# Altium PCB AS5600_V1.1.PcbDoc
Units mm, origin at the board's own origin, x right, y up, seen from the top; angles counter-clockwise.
Board outline 34 x 34 mm, 2 copper layers (Top Layer, Bottom Layer); 12 components, 7 nets, 31 pads, 49 vias.
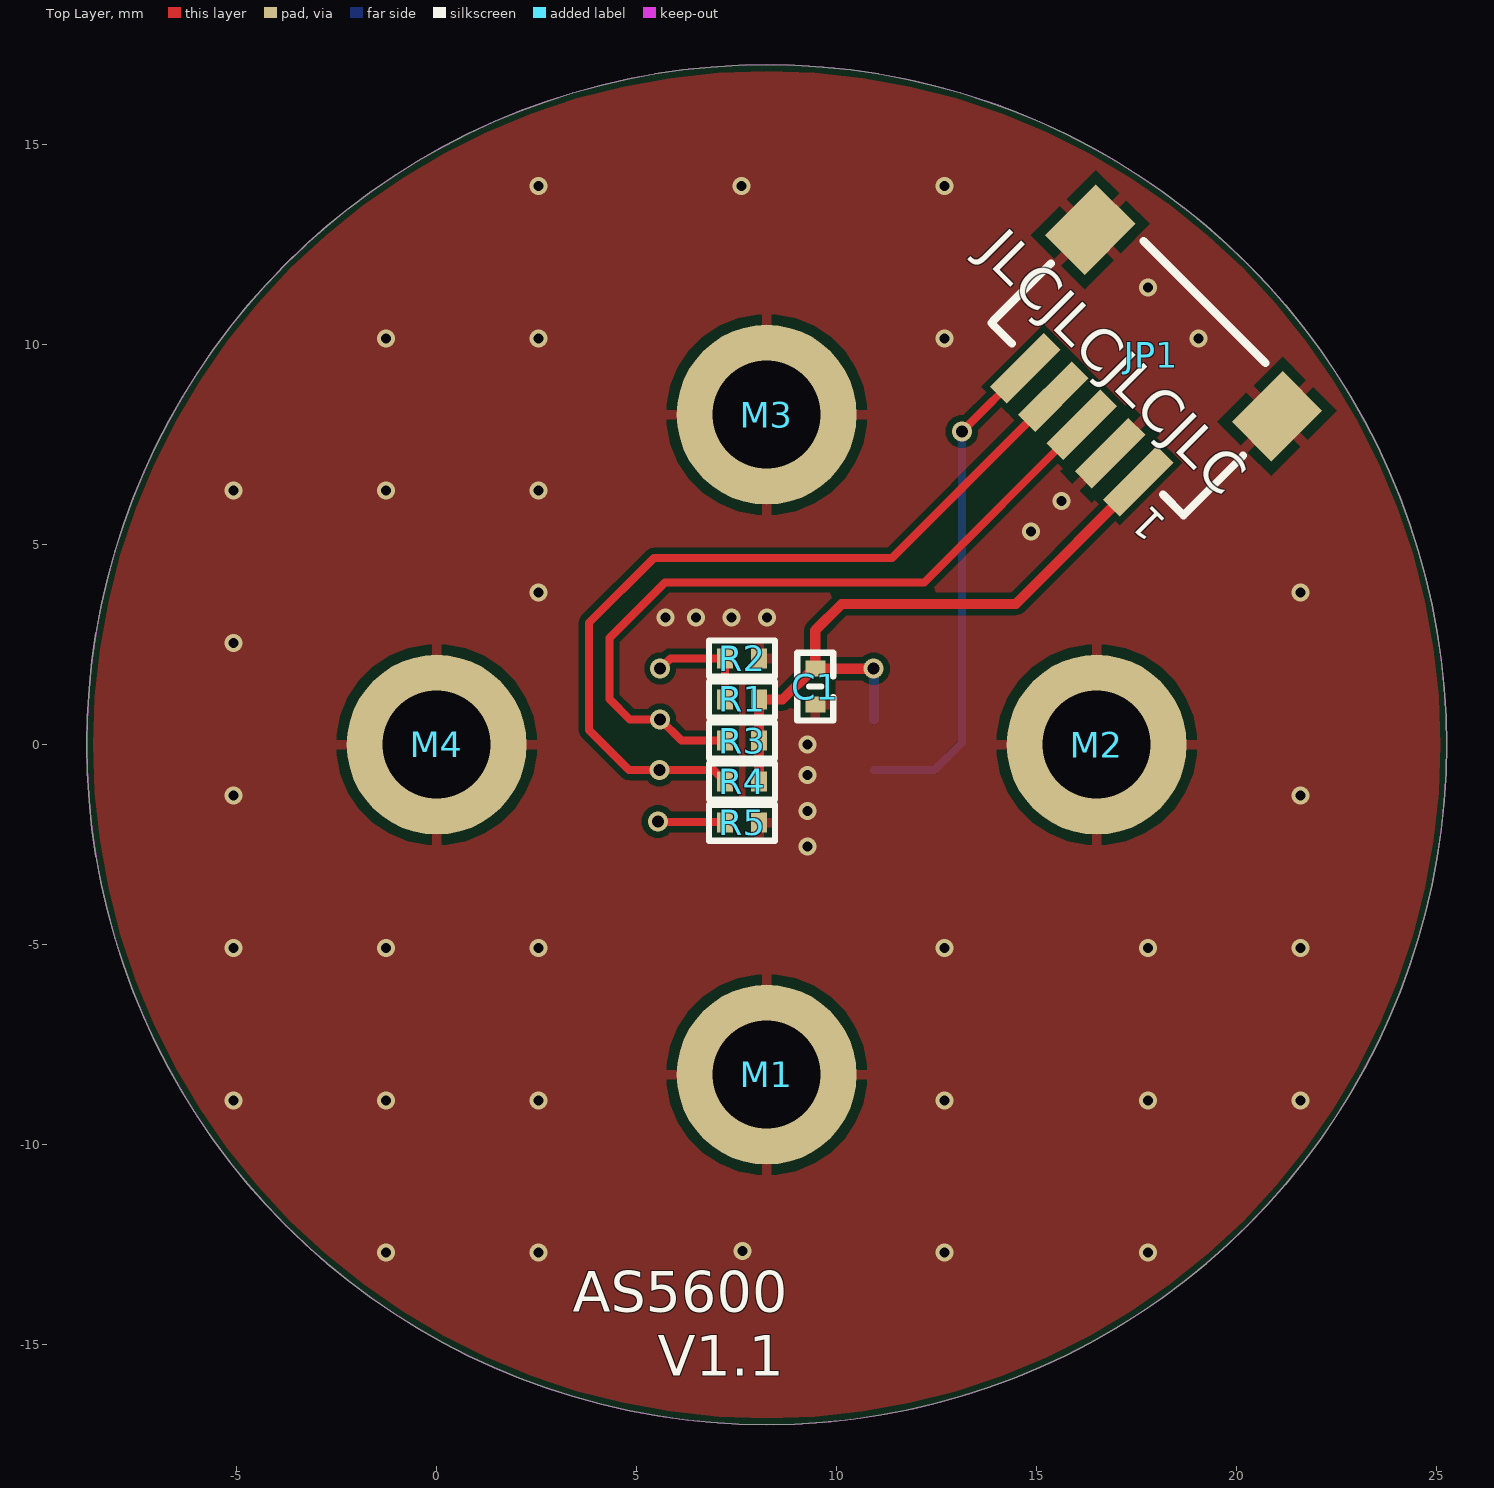
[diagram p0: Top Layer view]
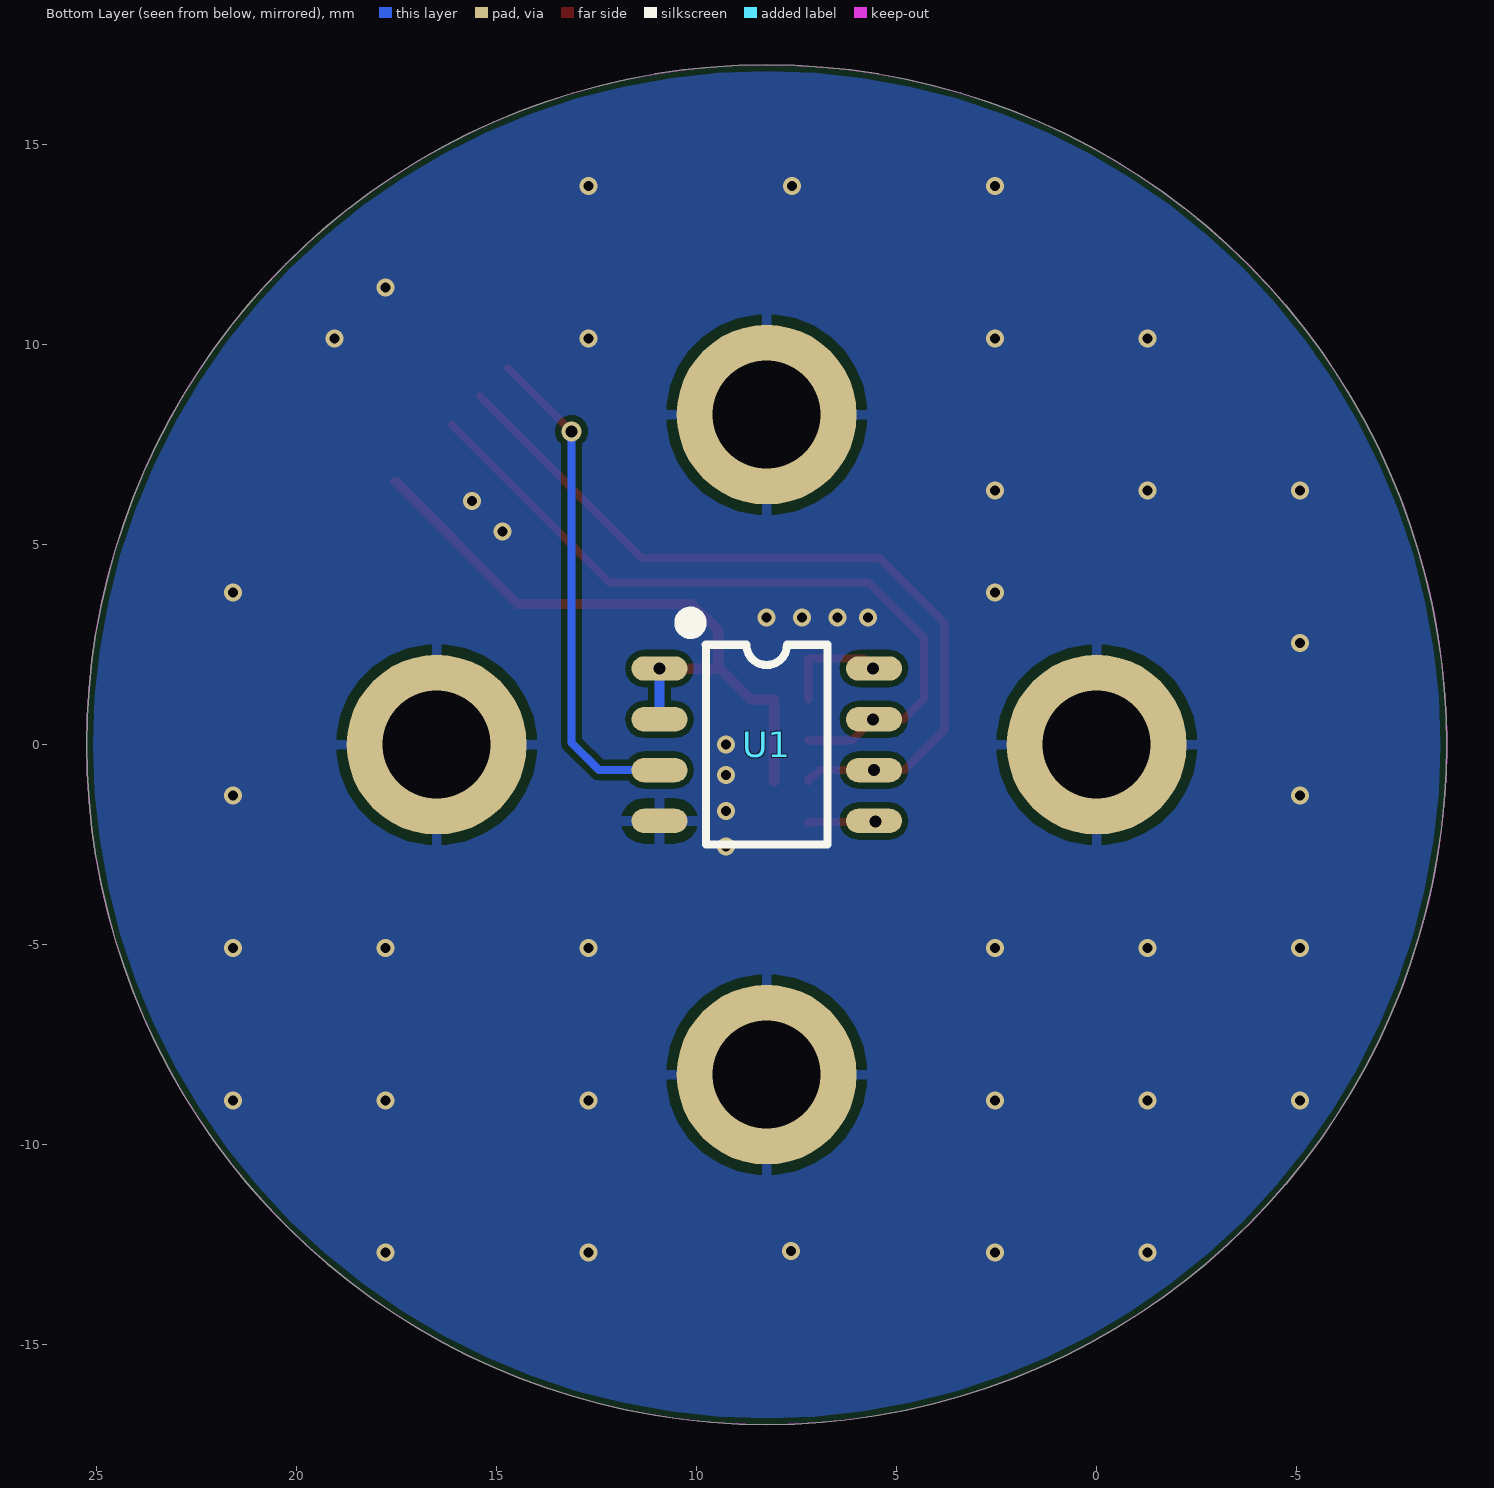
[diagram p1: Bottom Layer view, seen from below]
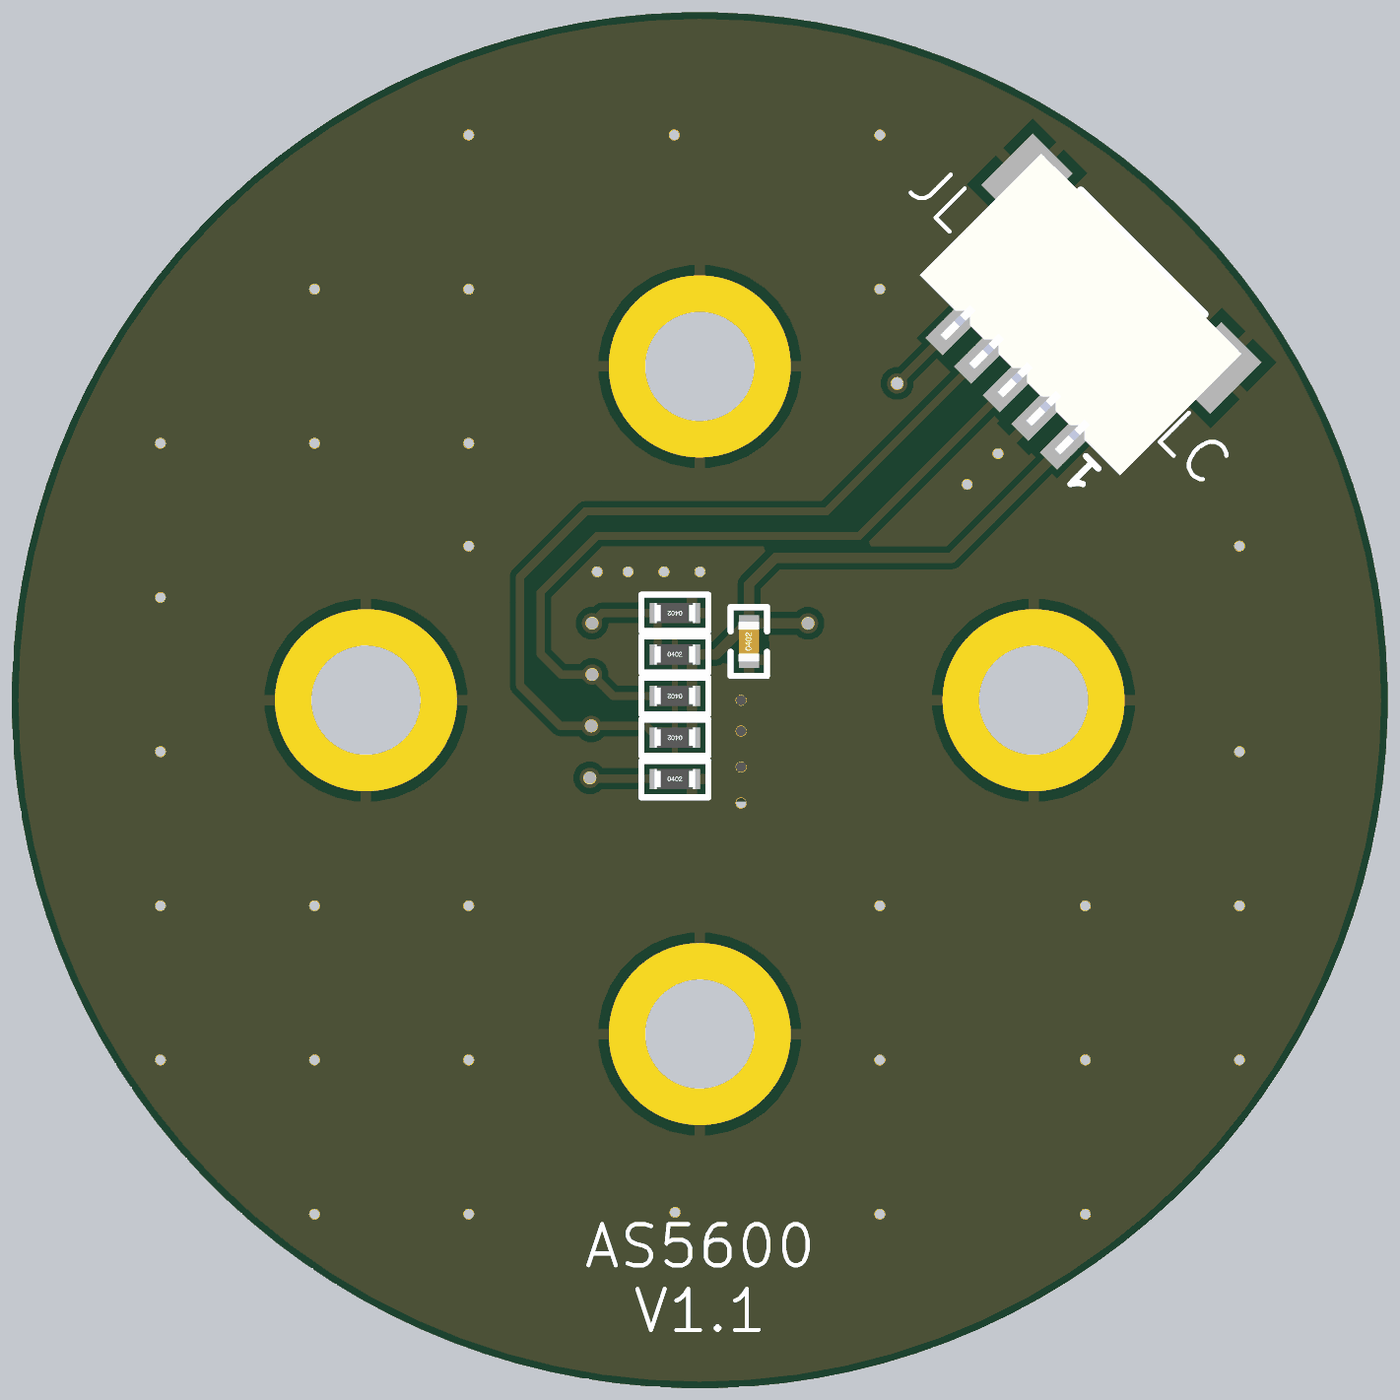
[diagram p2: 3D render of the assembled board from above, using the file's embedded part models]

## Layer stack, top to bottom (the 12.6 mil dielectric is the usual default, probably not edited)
Top Solder: solder mask 0.0102, Solder Resist, Dk 3.5
Top Layer: signal copper 0.0356
Dielectric 1: dielectric 0.32, FR-4, Dk 4.8
Bottom Layer: signal copper 0.0356
Bottom Solder: solder mask 0.0102, Solder Resist, Dk 3.5

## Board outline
-8.75,0 ccw(c8.25,0) 8.25,-17 ccw(c8.25,0) 25.25,0 ccw(c8.25,0) 8.25,17 ccw(c8.25,0)

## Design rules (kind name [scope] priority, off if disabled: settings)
Clearance [All] p1: gap=0.152 ignorepadtopadclearanceinfootprint=FALSE
HoleToHoleClearance [All] p1: gap=0 allowstackedmicrovias=TRUE
MinimumSolderMaskSliver [All] p1: minsoldermaskwidth=0
PolygonConnect M2.5 [HasFootprint('M2焊盘')] p1: connectstyle=Direct reliefconductorwidth=0.254 reliefentries=4 polygonreliefangle="90 Angle" airgapwidth=0.254
PolygonConnect [All] p2: thpad.connectstyle=Relief thpad.reliefconductorwidth=0.254 thpad.reliefentries=4 thpad.polygonreliefangle="90 Angle" thpad.airgapwidth=0.254 smdpad.connectstyle=Relief smdpad.reliefconductorwidth=0.254 smdpad.reliefentries=4 smdpad.polygonreliefangle="90 Angle" smdpad.airgapwidth=0.254 via.connectstyle=Direct via.reliefconductorwidth=0.254 via.reliefentries=4 via.polygonreliefangle="90 Angle" via.airgapwidth=0.254
RoomDefinition AS5600 [InComponentClass('AS5600')] p1: confinementstyle=ConfineIn formatcopy=TRUE lockcomponents=FALSE outline -75.128,-76.456 -24.328,-76.456 -24.328,-51.056 -75.128,-51.056
RoutingVias [All] p1: holewidth=0.25 width=0.45 viastyle="Through Hole" minholewidth=0.25 minwidth=0.45 maxholewidth=0.6 maxwidth=0.8
SilkToSilkClearance [All] p1: silktosilkclearance=0
SilkToSolderMaskClearance [IsPad] p1: minsilkscreentomaskgap=0 clearancetoexposedcopper=TRUE
SolderMaskExpansion [IsVia] p1: expansion=0.102 istentingtop=TRUE useseparateexpansions=TRUE expansionbottom=0.102 istentingbottom=TRUE
Width [All] p1: maxlimit=0.762 minlimit=0.152 preferedwidth=0.152
26 further rules are at their usual default settings.

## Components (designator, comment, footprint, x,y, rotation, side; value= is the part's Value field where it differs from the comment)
C1 "0.1uF" C0402_L 9.463,1.451 r90 top
JP1 "CON-5P" SH1.0-WT-5P 17.399,9.271 r135 top
M1 "M2.5" M2.5 8.25,-8.25 r0 top
M2 "M2.5" M2.5 16.5,0 r0 top
M3 "M2.5" M2.5 8.25,8.25 r0 top
M4 "M2.5" M2.5 0,0 r0 top
R1 "NC" R0402_L 7.635,1.132 r0 top
R2 "NC" R0402_L 7.635,2.159 r180 top
R3 "4.7K" R0402_L 7.635,0.105 r180 top
R4 "4.7K" R0402_L 7.635,-0.922 r180 top
R5 "4.7K" R0402_L 7.635,-1.95 r0 top
U1 "AS5600" SOIC-8L 8.25,0 r180 bottom locked

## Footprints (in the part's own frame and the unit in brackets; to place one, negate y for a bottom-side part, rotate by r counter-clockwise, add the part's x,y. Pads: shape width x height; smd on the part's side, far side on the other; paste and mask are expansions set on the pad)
C0402_L [mm] "无极性贴片电容"
  rect 0.4x0.5 smd: 1(-0.45,0) 2(0.45,0)
  silkscreen extent -0.85,-0.45 0.85,0.45, body extent -0.5,-0.26 0.5,0.26, height 0.54
M2.5 [mm]
  round 4.5 hole 2.7: 1(0,0)
R0402_L [mm] "1/16W贴片电阻"
  rect 0.4x0.5 smd: 1(-0.425,0) 2(0.425,0)
  silkscreen extent -0.82,-0.45 0.83,0.45, body extent -0.5,-0.25 0.5,0.25, height 0.3
SH1.0-WT-5P [mm] "SH1.0连接器-卧贴-5P      来自淘宝卖家ID：黄晶宝石"
  rect 1.4x1.8 smd: 0(-3.3,-1.8) 0(3.3,-1.8)
  rect 0.6x1.9 smd: 1(-2,1.8) 2(-1,1.8) 3(0,1.8) 4(1,1.8) 5(2,1.8)
  silkscreen extent -3.4,-2.54 3.4,1.6, body extent -3.5,-2.5 3.5,2.45, height 2.9
SOIC-8L [mm] "封装库来自淘宝卖家 ID：黄晶宝石，其他均为盗版"
  oval 1.397x0.61 smd: 1(-2.68,1.905) 2(-2.68,0.635) 3(-2.68,-0.635) 4(-2.68,-1.905) 5(2.68,-1.905) 6(2.68,-0.635) 7(2.68,0.635) 8(2.68,1.905)
  silkscreen extent -2.06,-2.5 1.52,3.2, body extent -3,-2.5 3,2.5, height 1.9

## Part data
C1: library part C, "贴片电容"
JP1: library part "Header 5", "5P连接器"
M1 M2 M3 M4: library part M2系列, "M2孔支撑柱"
R1 R2 R3 R4 R5: library part R, "贴片电阻"
U1: "12bit 磁编码器"

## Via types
v1: diameter 0.45, hole 0.25, Top Layer to Bottom Layer, tented both sides, 43 vias
v2: diameter 0.5, hole 0.3, Top Layer to Bottom Layer, tented both sides, 6 vias

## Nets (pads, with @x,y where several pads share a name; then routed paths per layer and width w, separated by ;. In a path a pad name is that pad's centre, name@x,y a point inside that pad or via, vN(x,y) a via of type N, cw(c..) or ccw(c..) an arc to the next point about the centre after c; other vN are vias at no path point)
AS5600_OUT: JP1.5 U1.3 | length 12.5
  Top Layer w0.203: v2(13.129,7.829) JP1.5
  Bottom Layer w0.203: U1.3 12.446,-0.635 13.129,0.048 v2(13.129,7.829)
AS5600_SCL: JP1.3 R3.2 U1.7 | length 18.9
  Top Layer w0.203: R3.2 6.118,0.105 v2(5.588,0.635) 4.826,0.635 4.318,1.143 4.318,2.667 5.711,4.06 12.188,4.06 JP1.3
  Bottom Layer w0.203: U1.7 v2(5.588,0.635)
AS5600_SDA: JP1.4 R4.2 U1.6 | length 20.6
  Top Layer w0.203: R4.2 7.21,-0.872 7.112,-0.774 7.062,-0.774 6.923,-0.635 v2(5.57,-0.635) 4.81,-0.635 3.81,0.365 3.81,3.048 5.431,4.669 11.383,4.669 JP1.4
GND: C1.1 JP1.0 JP1.2 M1.1 M2.1 M3.1 M4.1 R2.1 R5.2 U1.4
  other v1: -1.27,-12.7 2.54,-12.7 12.7,-12.7 17.78,-12.7 7.64,-12.655 -5.08,-8.89 -1.27,-8.89 2.54,-8.89 12.7,-8.89 17.78,-8.89 21.59,-8.89 -5.08,-5.08 -1.27,-5.08 2.54,-5.08 12.7,-5.08 17.78,-5.08 21.59,-5.08 9.271,-2.54 9.271,-1.651 -5.08,-1.27 21.59,-1.27 9.271,-0.762 9.271,0 -5.08,2.54 5.715,3.175 6.477,3.175 7.366,3.175 8.255,3.175 2.54,3.81 21.59,3.81 14.859,5.334 15.621,6.096 -5.08,6.35 -1.27,6.35 2.54,6.35 -1.27,10.16 2.54,10.16 12.7,10.16 19.05,10.16 17.78,11.43 2.54,13.97 7.62,13.97 12.7,13.97
NetR1_1: R1.1 R2.2 U1.8 | length 2.8
  Top Layer w0.203: v2(5.588,1.905) 5.842,2.159 R2.2 R1.1
  Bottom Layer w0.203: U1.8 v2(5.588,1.905)
NetR5_1: R5.1 U1.5 | length 1.7
  Top Layer w0.203: v2(5.534,-1.919) 5.549,-1.934 7.195,-1.934 R5.1
  Bottom Layer w0.203: v2(5.534,-1.919) 5.556,-1.919 U1.5
VCC_3V3: C1.2 JP1.1 R1.2 R3.1 R4.1 U1.1 U1.2 | length 17.1
  Top Layer w0.254: R4.1 R3.1 R1.2 8.645,1.132 9.413,1.9 C1.2 ; v2(10.925,1.9) C1.2 ; JP1.1 14.476,3.519 10.123,3.519 9.463,2.859 C1.2
  Bottom Layer w0.254: U1.2 10.93,1.896 v2(10.925,1.9) U1.1

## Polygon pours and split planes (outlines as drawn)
GND on Top Layer "GND_L01_P000" (solid, remove dead copper, pour order 0): -9.144,17.399 -9.144,-17.272 25.781,-17.272 25.781,17.399
GND on Bottom Layer "GND_L02_P001" (solid, remove dead copper, pour order 1): -9.144,17.399 -9.144,-17.272 25.781,-17.272 25.781,17.399

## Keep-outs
Keep-Out Layer:
  circle w0.013: c8.25,0 r17

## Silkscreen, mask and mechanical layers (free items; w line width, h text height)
Top Overlay:
  text "JLCJLCJLCJLC" at 13.51,12.272 h1.02 r315
  text "AS5600" at 3.401,-14.173 h1.02
  text "V1.1" at 5.527,-15.773 h1.02
Mechanical 1:
  circle w0.013: c8.25,0 r17
Mechanical 2:
  circle w0.013: c8.25,-8.25 r1.25
  circle w0.013: c16.5,0 r1.25
  circle w0.013: c0,0 r1.25
  circle w0.013: c0,0 r1.25
  circle w0.013: c8.25,8.25 r1.25
  circle w0.013: c8.25,0 r17
Mechanical 3:
  circle w0.006: c0,0 r0.003
  circle w0.006: c16.5,-21.603 r0.003
  circle w0.006: c8.25,8.25 r0.003
  circle w0.006: c8.25,-8.25 r0.003
  circle w0.006: c20.951,11.3 r0.003
  circle w0.006: c-4.451,-11.3 r0.003
  circle w0.006: c8.754,9.394 r0.003
  circle w0.006: c7.746,7.106 r0.003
